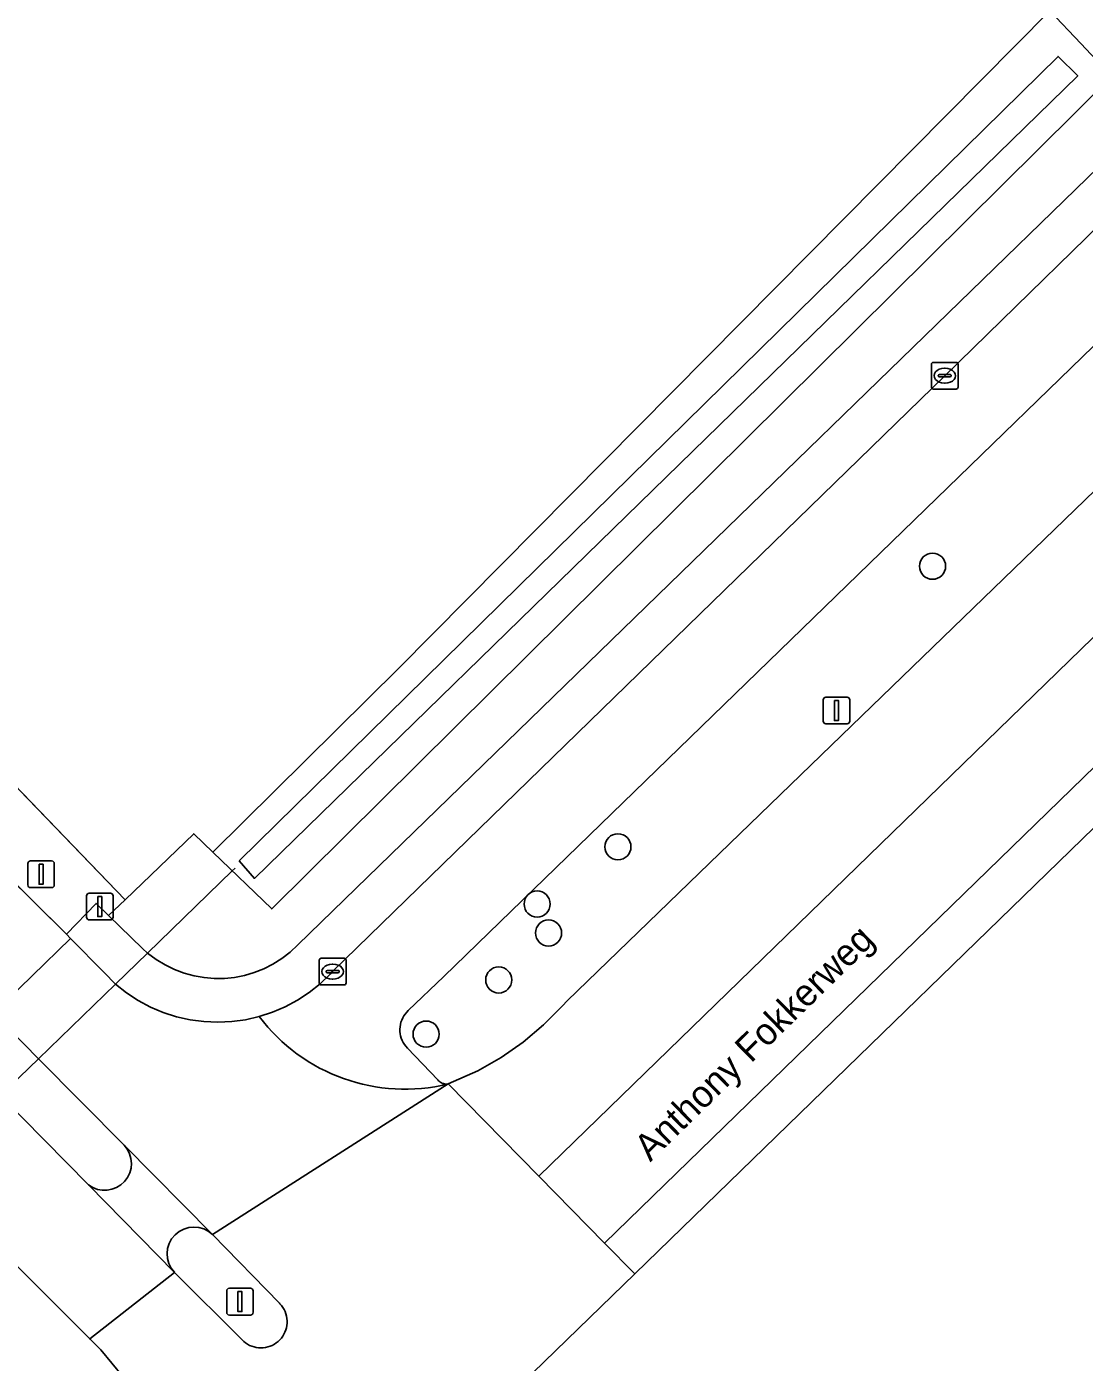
# Model space of a CAD drawing. Extents: x 156141 to 158132, y 385651 to 388333.
# Drawn here: x 156871.19 to 156910.79, y 385918.57 to 385968.56 of the extents above; entities that cross this region are included whole.
import ezdxf

# ---------------------------------------------------------------- set-up
doc = ezdxf.new("R2010")
doc.units = 0
for name, color, linetype in [('IMGEO_Berm_groen', 7, 'Continuous'), ('IMGEO_Boom', 7, 'Continuous'), ('IMGEO_Bouwland', 7, 'Continuous'), ('IMGEO_Duiker', 7, 'Continuous'), ('IMGEO_Fietspad_gesloten', 7, 'Continuous'), ('IMGEO_Fietspad_open', 7, 'Continuous'), ('IMGEO_Grasland_overig', 7, 'Continuous'), ('IMGEO_Groenvoorziening', 7, 'Continuous'), ('IMGEO_Kolk', 7, 'Continuous'), ('IMGEO_Lichtmast', 7, 'Continuous'), ('IMGEO_Oever', 7, 'Continuous'), ('IMGEO_Openbare_ruimte_label', 7, 'Continuous'), ('IMGEO_Rijbaan_lokaal_gesloten', 7, 'Continuous'), ('IMGEO_Rijbaan_lokaal_open', 7, 'Continuous'), ('IMGEO_Rijbaan_regionaal_gesloten', 7, 'Continuous'), ('IMGEO_Verkeersbordpaal', 7, 'Continuous'), ('IMGEO_Verkeerseiland_open', 7, 'Continuous'), ('IMGEO_Voetpad_open', 7, 'Continuous'), ('IMGEO_Waterloop', 7, 'Continuous')]:
    doc.layers.add(name, color=color, linetype=linetype)

msp = doc.modelspace()

# ---------------------------------------------------------------- linework, layer by layer
at = {"layer": 'IMGEO_Berm_groen'}
for points in [[(156930.003, 385974.918), (156886.812, 385933.009), (156885.478, 385931.729), (156885.417, 385931.668), (156885.361, 385931.601), (156885.312, 385931.53), (156885.269, 385931.455), (156885.233, 385931.376), (156885.204, 385931.294), (156885.183, 385931.21), (156885.169, 385931.124), (156885.163, 385931.038), (156885.165, 385930.951), (156885.174, 385930.865), (156885.191, 385930.78), (156885.216, 385930.697), (156885.248, 385930.616), (156885.287, 385930.539), (156885.333, 385930.465), (156885.385, 385930.396), (156885.45, 385930.325), (156886.578, 385929.141), (156886.602, 385929.112), (156886.629, 385929.086), (156886.659, 385929.062), (156886.69, 385929.041), (156886.723, 385929.022), (156886.757, 385929.007), (156886.793, 385928.995), (156886.83, 385928.986), (156886.867, 385928.98), (156886.904, 385928.978), (156886.942, 385928.979), (156886.974, 385928.983), (156888.076, 385929.479), (156888.949, 385929.977), (156889.774, 385930.55), (156890.545, 385931.196), (156891.255, 385931.907), (156891.426, 385932.099), (156932.102, 385971.44)], [(156874.788, 385918.027), (156873.964, 385919.033), (156873.553, 385919.437), (156867.279, 385925.705), (156865.275, 385923.762), (156865.686, 385922.841), (156867.113, 385917.692)]]:
    msp.add_lwpolyline(points, dxfattribs=at)
at = {"layer": 'IMGEO_Boom'}
for centre in [(156905.108, 385948.364), (156893.327, 385937.861), (156890.303, 385935.719), (156890.729, 385934.635), (156888.864, 385932.877), (156886.145, 385930.849)]:
    msp.add_circle(centre, 0.489, dxfattribs=at)
at = {"layer": 'IMGEO_Bouwland'}
msp.add_lwpolyline([(156850.754, 385950.548), (156852.463, 385950.284), (156855.652, 385949.539), (156859.447, 385948.19), (156861.712, 385947.117), (156863.64, 385946.028), (156865.038, 385945.128), (156867.151, 385943.555), (156868.367, 385942.514), (156869.913, 385941.02), (156874.876, 385935.88), (156877.444, 385938.348), (156878.163, 385937.657), (156885.11, 385944.531), (156909.503, 385969.158), (156915.884, 385975.312), (156925.124, 385983.726), (156925.232, 385984.523), (156902.704, 386022.826), (156897.961, 386029.254), (156853.147, 386019.451), (156848.312, 386019.157)], dxfattribs=at)
at = {"layer": 'IMGEO_Duiker'}
msp.add_lwpolyline([(156864.371, 385922.885), (156865.275, 385923.762), (156867.279, 385925.705), (156870.21, 385928.547), (156871.635, 385929.928), (156874.513, 385932.719), (156875.714, 385933.884), (156878.887, 385936.96), (156878.995, 385937.065)], dxfattribs=at)
at = {"layer": 'IMGEO_Fietspad_gesloten'}
for points in [[(156939.898, 385988.199), (156929.654, 385978.802), (156929.144, 385978.317), (156928.848, 385978.036), (156921.473, 385971.021), (156905.562, 385955.495), (156882.643, 385933.19), (156882.555, 385933.096), (156882.177, 385932.735), (156881.769, 385932.409), (156881.333, 385932.122), (156880.873, 385931.874), (156880.393, 385931.668), (156879.896, 385931.506)], [(156886.974, 385928.983), (156886.942, 385928.979), (156886.904, 385928.978), (156886.867, 385928.98), (156886.83, 385928.986), (156886.793, 385928.995), (156886.757, 385929.007), (156886.723, 385929.022), (156886.69, 385929.041), (156886.659, 385929.062), (156886.629, 385929.086), (156886.602, 385929.112), (156886.578, 385929.141), (156885.45, 385930.325), (156885.385, 385930.396), (156885.333, 385930.465), (156885.287, 385930.539), (156885.248, 385930.616), (156885.216, 385930.697), (156885.191, 385930.78), (156885.174, 385930.865), (156885.165, 385930.951), (156885.163, 385931.038), (156885.169, 385931.124), (156885.183, 385931.21), (156885.204, 385931.294), (156885.233, 385931.376), (156885.269, 385931.455), (156885.312, 385931.53), (156885.361, 385931.601), (156885.417, 385931.668), (156885.478, 385931.729), (156886.812, 385933.009), (156930.003, 385974.918)]]:
    msp.add_lwpolyline(points, dxfattribs=at)
msp.add_arc((156885.355, 385935.632), 6.843, 217.0806, 283.6816, dxfattribs=at)
at = {"layer": 'IMGEO_Fietspad_open'}
for points in [[(156878.148, 385923.344), (156874.845, 385926.689)], [(156873.5, 385925.207), (156876.718, 385921.932)]]:
    msp.add_lwpolyline(points, dxfattribs=at)
for centre, radius, start, end in [((156874.108, 385926.006), 1.004, 232.7427, 42.8063), ((156877.45, 385922.621), 1.005, 46.0245, 223.2497)]:
    msp.add_arc(centre, radius, start, end, dxfattribs=at)
at = {"layer": 'IMGEO_Grasland_overig'}
msp.add_lwpolyline([(156866.966, 385940.233), (156872.684, 385934.595), (156873.79, 385935.743), (156874.258, 385935.286), (156874.876, 385935.88), (156869.913, 385941.02), (156868.367, 385942.514), (156867.151, 385943.555), (156865.038, 385945.128), (156863.64, 385946.028), (156861.712, 385947.117), (156859.447, 385948.19), (156855.652, 385949.539), (156852.463, 385950.284), (156850.754, 385950.548), (156847.012, 385950.806), (156823.489, 385951.065), (156739.662, 385952.666), (156453.016, 385994.658)], dxfattribs=at)
at = {"layer": 'IMGEO_Groenvoorziening'}
for points in [[(156941.728, 385998.626), (156934.836, 385992.57), (156936.116, 385991.43), (156936.687, 385990.376), (156936.498, 385989.652), (156929.281, 385982.845), (156927.241, 385980.92), (156927.233, 385980.913), (156918.862, 385973.017), (156917.513, 385973.337), (156916.699, 385974.324), (156915.884, 385975.312), (156909.503, 385969.158), (156910.659, 385967.93), (156911.816, 385966.701), (156880.365, 385935.537), (156878.163, 385937.657), (156877.444, 385938.348), (156874.876, 385935.88), (156874.258, 385935.286), (156875.523, 385934.052), (156875.714, 385933.884)], [(156881.347, 385934.192), (156928.285, 385979.781), (156928.807, 385980.25), (156947.083, 385996.683)]]:
    msp.add_lwpolyline(points, dxfattribs=at)
msp.add_arc((156878.364, 385937.09), 4.159, 230.427, 315.8324, dxfattribs=at)
at = {"layer": 'IMGEO_Kolk'}
for p, q in [((156905.064, 385955.07), (156905.064, 385955.922)), ((156905.139, 385955.996), (156905.991, 385955.996)), ((156906.065, 385955.922), (156906.065, 385955.07)), ((156905.323, 385955.49), (156905.323, 385955.502)), ((156905.761, 385955.453), (156905.363, 385955.453)), ((156905.366, 385955.539), (156905.764, 385955.539)), ((156905.552, 385955.776), (156905.577, 385955.776)), ((156905.807, 385955.502), (156905.807, 385955.49)), ((156905.991, 385954.996), (156905.139, 385954.996)), ((156905.575, 385955.216), (156905.55, 385955.216)), ((156882.145, 385932.765), (156882.145, 385933.617)), ((156882.22, 385933.691), (156883.072, 385933.691)), ((156882.633, 385933.471), (156882.658, 385933.471)), ((156883.146, 385933.617), (156883.146, 385932.765)), ((156882.404, 385933.185), (156882.404, 385933.197)), ((156882.842, 385933.148), (156882.444, 385933.148)), ((156882.447, 385933.234), (156882.845, 385933.234)), ((156882.656, 385932.911), (156882.631, 385932.911)), ((156882.888, 385933.197), (156882.888, 385933.185)), ((156883.072, 385932.691), (156882.22, 385932.691))]:
    msp.add_line(p, q, dxfattribs=at)
for points in [[(156905.064, 385955.07), (156905.064, 385955.922)], [(156905.139, 385955.996), (156905.991, 385955.996)], [(156906.065, 385955.922), (156906.065, 385955.07)], [(156905.991, 385954.996), (156905.139, 385954.996)], [(156882.145, 385932.765), (156882.145, 385933.617)], [(156882.22, 385933.691), (156883.072, 385933.691)], [(156883.146, 385933.617), (156883.146, 385932.765)], [(156883.072, 385932.691), (156882.22, 385932.691)]]:
    msp.add_lwpolyline(points, dxfattribs=at)
for centre, radius, start, end in [((156905.141, 385955.92), 0.0765, 91.552, 178.448), ((156905.141, 385955.92), 0.0765, 91.552, 178.448), ((156905.989, 385955.92), 0.0765, 1.552, 88.448), ((156905.989, 385955.92), 0.0765, 1.552, 88.448), ((156905.363, 385955.499), 0.0403, 85.8775, 175.7526), ((156905.36, 385955.489), 0.0366, 178.938, 274.7102), ((156905.764, 385955.496), 0.043, 264.8664, 352.4533), ((156905.768, 385955.501), 0.0386, 1.7309, 96.639), ((156905.141, 385955.072), 0.0765, 181.552, 268.448), ((156905.141, 385955.072), 0.0765, 181.552, 268.448), ((156905.989, 385955.072), 0.0765, 271.552, 358.448), ((156905.989, 385955.072), 0.0765, 271.552, 358.448), ((156882.222, 385933.615), 0.0765, 91.552, 178.448), ((156882.222, 385933.615), 0.0765, 91.552, 178.448), ((156883.07, 385933.615), 0.0765, 1.552, 88.448), ((156883.07, 385933.615), 0.0765, 1.552, 88.448), ((156882.444, 385933.194), 0.0403, 85.8775, 175.7526), ((156882.441, 385933.184), 0.0366, 178.938, 274.7102), ((156882.845, 385933.191), 0.043, 264.8664, 352.4533), ((156882.849, 385933.196), 0.0386, 1.7309, 96.639), ((156882.222, 385932.767), 0.0765, 181.552, 268.448), ((156882.222, 385932.767), 0.0765, 181.552, 268.448), ((156883.07, 385932.767), 0.0765, 271.552, 358.448), ((156883.07, 385932.767), 0.0765, 271.552, 358.448)]:
    msp.add_arc(centre, radius, start, end, dxfattribs=at)
for centre, major_axis, ratio, start_param, end_param in [((156905.551, 385955.496), (-0.387, 0.002), 0.722429, 4.712389, 7.853982), ((156905.576, 385955.496), (-0.39, 0.002), 0.717154, 1.570796, 4.712389), ((156882.632, 385933.191), (-0.387, 0.002), 0.722429, 4.712389, 7.853982), ((156882.657, 385933.191), (-0.39, 0.002), 0.717154, 1.570796, 4.712389)]:
    msp.add_ellipse(centre, major_axis=major_axis, ratio=ratio, start_param=start_param, end_param=end_param, dxfattribs=at)
at = {"layer": 'IMGEO_Lichtmast'}
for p, q in [((156901.115, 385943.464), (156901.905, 385943.464)), ((156901.905, 385943.464), (156901.115, 385943.464)), ((156901.015, 385942.564), (156901.015, 385943.364)), ((156901.015, 385943.364), (156901.015, 385942.564)), ((156902.005, 385943.364), (156902.005, 385942.564)), ((156902.005, 385942.564), (156902.005, 385943.364)), ((156901.905, 385942.464), (156901.115, 385942.464)), ((156901.115, 385942.464), (156901.905, 385942.464)), ((156871.234, 385936.432), (156871.234, 385937.232)), ((156871.234, 385937.232), (156871.234, 385936.432)), ((156871.334, 385937.332), (156872.124, 385937.332)), ((156872.124, 385937.332), (156871.334, 385937.332)), ((156872.224, 385937.232), (156872.224, 385936.432)), ((156872.224, 385936.432), (156872.224, 385937.232)), ((156872.124, 385936.332), (156871.334, 385936.332)), ((156871.334, 385936.332), (156872.124, 385936.332)), ((156878.678, 385920.435), (156878.678, 385921.235)), ((156878.678, 385921.235), (156878.678, 385920.435)), ((156878.778, 385921.335), (156879.568, 385921.335)), ((156879.568, 385921.335), (156878.778, 385921.335)), ((156879.668, 385921.235), (156879.668, 385920.435)), ((156879.668, 385920.435), (156879.668, 385921.235)), ((156879.568, 385920.335), (156878.778, 385920.335)), ((156878.778, 385920.335), (156879.568, 385920.335))]:
    msp.add_line(p, q, dxfattribs=at)
for points in [[(156901.435, 385943.339), (156901.585, 385943.339), (156901.585, 385942.589), (156901.435, 385942.589), (156901.435, 385943.339)], [(156871.654, 385937.207), (156871.804, 385937.207), (156871.804, 385936.457), (156871.654, 385936.457), (156871.654, 385937.207)], [(156879.098, 385921.21), (156879.248, 385921.21), (156879.248, 385920.46), (156879.098, 385920.46), (156879.098, 385921.21)]]:
    msp.add_lwpolyline(points, dxfattribs=at)
for centre, start, end in [((156901.115, 385943.364), 90, 180), ((156901.115, 385943.364), 90, 180), ((156901.905, 385943.364), 0, 90), ((156901.905, 385943.364), 360, 90), ((156901.115, 385942.564), 180, 270), ((156901.115, 385942.564), 180, 270), ((156901.905, 385942.564), 270, 0), ((156901.905, 385942.564), 270, 0), ((156871.334, 385937.232), 90, 180), ((156871.334, 385937.232), 90, 180), ((156872.124, 385937.232), 0, 90), ((156872.124, 385937.232), 360, 90), ((156871.334, 385936.432), 180, 270), ((156871.334, 385936.432), 180, 270), ((156872.124, 385936.432), 270, 0), ((156872.124, 385936.432), 270, 0), ((156878.778, 385921.235), 90, 180), ((156878.778, 385921.235), 90, 180), ((156879.568, 385921.235), 0, 90), ((156879.568, 385921.235), 360, 90), ((156878.778, 385920.435), 180, 270), ((156878.778, 385920.435), 180, 270), ((156879.568, 385920.435), 270, 0), ((156879.568, 385920.435), 270, 0)]:
    msp.add_arc(centre, 0.1, start, end, dxfattribs=at)
at = {"layer": 'IMGEO_Oever'}
for points in [[(156909.503, 385969.158), (156885.11, 385944.531), (156878.163, 385937.657), (156880.365, 385935.537), (156911.816, 385966.701), (156910.659, 385967.93)], [(156879.147, 385937.336), (156909.805, 385967.446), (156910.544, 385966.727), (156879.719, 385936.678)]]:
    msp.add_lwpolyline(points, close=True, dxfattribs=at)
at = {"layer": 'IMGEO_Rijbaan_lokaal_gesloten'}
msp.add_lwpolyline([(156879.896, 385931.506), (156879.387, 385931.39), (156878.87, 385931.319), (156878.348, 385931.294), (156877.826, 385931.316), (156877.308, 385931.385), (156876.799, 385931.5), (156876.302, 385931.66), (156875.821, 385931.863), (156875.36, 385932.109), (156874.923, 385932.395), (156874.513, 385932.719), (156874.086, 385933.151), (156872.828, 385934.428), (156869.95, 385931.628), (156871.635, 385929.928), (156874.845, 385926.689), (156878.148, 385923.344), (156886.974, 385928.983)], dxfattribs=at)
msp.add_lwpolyline([(156873.5, 385925.207), (156870.21, 385928.547), (156868.557, 385930.225), (156865.574, 385927.365), (156866.774, 385926.21), (156867.279, 385925.705), (156873.553, 385919.437), (156876.718, 385921.932)], close=True, dxfattribs=at)
msp.add_arc((156885.355, 385935.632), 6.843, 217.0806, 283.6816, dxfattribs=at)
at = {"layer": 'IMGEO_Rijbaan_lokaal_open'}
msp.add_lwpolyline([(156869.95, 385931.628), (156872.828, 385934.428), (156872.684, 385934.595), (156866.966, 385940.233)], dxfattribs=at)
at = {"layer": 'IMGEO_Rijbaan_regionaal_gesloten'}
for points in [[(156934.501, 385968.404), (156934.45, 385968.491), (156932.494, 385971.832), (156932.102, 385971.44), (156891.426, 385932.099), (156891.255, 385931.907), (156890.545, 385931.196), (156889.774, 385930.55), (156888.949, 385929.977), (156888.076, 385929.479), (156886.974, 385928.983), (156890.369, 385925.526)], [(156936.323, 385965.294), (156934.501, 385968.404), (156890.369, 385925.526), (156892.83, 385923.021)], [(156893.955, 385921.876), (156937.167, 385963.852), (156936.323, 385965.294), (156892.83, 385923.021)]]:
    msp.add_lwpolyline(points, close=True, dxfattribs=at)
msp.add_lwpolyline([(156879.95, 385908.272), (156893.955, 385921.876), (156892.83, 385923.021), (156890.369, 385925.526), (156886.974, 385928.983), (156878.148, 385923.344), (156880.657, 385920.772), (156880.674, 385920.754), (156880.731, 385920.688), (156880.782, 385920.617), (156880.827, 385920.541), (156880.864, 385920.462), (156880.895, 385920.38), (156880.917, 385920.295), (156880.933, 385920.209), (156880.94, 385920.121), (156880.94, 385920.034), (156880.931, 385919.947), (156880.915, 385919.861), (156880.892, 385919.776), (156880.861, 385919.694), (156880.822, 385919.615), (156880.777, 385919.54), (156880.725, 385919.47), (156880.668, 385919.404), (156880.604, 385919.343), (156880.536, 385919.289), (156880.462, 385919.241), (156880.385, 385919.199), (156880.305, 385919.165), (156880.221, 385919.138), (156880.136, 385919.118), (156880.049, 385919.107), (156879.961, 385919.103), (156879.874, 385919.107), (156879.787, 385919.118), (156879.702, 385919.138), (156879.618, 385919.165), (156879.538, 385919.199), (156879.46, 385919.24), (156879.387, 385919.288), (156879.319, 385919.343), (156879.255, 385919.403), (156876.718, 385921.932), (156873.553, 385919.437), (156873.964, 385919.033), (156874.788, 385918.027)], dxfattribs=at)
at = {"layer": 'IMGEO_Verkeersbordpaal'}
for p, q in [((156873.433, 385935.224), (156873.433, 385936.024)), ((156873.433, 385936.024), (156873.433, 385935.224)), ((156873.533, 385936.124), (156874.323, 385936.124)), ((156874.323, 385936.124), (156873.533, 385936.124)), ((156874.423, 385936.024), (156874.423, 385935.224)), ((156874.423, 385935.224), (156874.423, 385936.024)), ((156874.323, 385935.124), (156873.533, 385935.124)), ((156873.533, 385935.124), (156874.323, 385935.124))]:
    msp.add_line(p, q, dxfattribs=at)
msp.add_lwpolyline([(156873.853, 385935.999), (156874.003, 385935.999), (156874.003, 385935.249), (156873.853, 385935.249), (156873.853, 385935.999)], dxfattribs=at)
for centre, start, end in [((156873.533, 385936.024), 90, 180), ((156873.533, 385936.024), 90, 180), ((156874.323, 385936.024), 0, 90), ((156874.323, 385936.024), 360, 90), ((156873.533, 385935.224), 180, 270), ((156873.533, 385935.224), 180, 270), ((156874.323, 385935.224), 270, 0), ((156874.323, 385935.224), 270, 0)]:
    msp.add_arc(centre, 0.1, start, end, dxfattribs=at)
at = {"layer": 'IMGEO_Verkeerseiland_open'}
for points in [[(156871.635, 385929.928), (156869.95, 385931.628)], [(156874.845, 385926.689), (156871.635, 385929.928)], [(156870.21, 385928.547), (156873.5, 385925.207)], [(156876.718, 385921.932), (156879.255, 385919.403), (156879.319, 385919.343), (156879.387, 385919.288), (156879.46, 385919.24), (156879.538, 385919.199), (156879.618, 385919.165), (156879.702, 385919.138), (156879.787, 385919.118), (156879.874, 385919.107), (156879.961, 385919.103), (156880.049, 385919.107), (156880.136, 385919.118), (156880.221, 385919.138), (156880.305, 385919.165), (156880.385, 385919.199), (156880.462, 385919.241), (156880.536, 385919.289), (156880.604, 385919.343), (156880.668, 385919.404), (156880.725, 385919.47), (156880.777, 385919.54), (156880.822, 385919.615), (156880.861, 385919.694), (156880.892, 385919.776), (156880.915, 385919.861), (156880.931, 385919.947), (156880.94, 385920.034), (156880.94, 385920.121), (156880.933, 385920.209), (156880.917, 385920.295), (156880.895, 385920.38), (156880.864, 385920.462), (156880.827, 385920.541), (156880.782, 385920.617), (156880.731, 385920.688), (156880.674, 385920.754), (156880.657, 385920.772), (156878.148, 385923.344)]]:
    msp.add_lwpolyline(points, dxfattribs=at)
for centre, radius, start, end in [((156874.108, 385926.006), 1.004, 232.7427, 42.8063), ((156877.45, 385922.621), 1.005, 46.0245, 223.2497)]:
    msp.add_arc(centre, radius, start, end, dxfattribs=at)
at = {"layer": 'IMGEO_Voetpad_open'}
for points in [[(156950.902, 386000), (156947.083, 385996.683), (156928.807, 385980.25), (156928.285, 385979.781), (156881.347, 385934.192)], [(156875.714, 385933.884), (156875.523, 385934.052), (156874.258, 385935.286), (156873.79, 385935.743), (156872.684, 385934.595), (156872.828, 385934.428), (156874.086, 385933.151), (156874.513, 385932.719), (156874.923, 385932.395), (156875.36, 385932.109), (156875.821, 385931.863), (156876.302, 385931.66), (156876.799, 385931.5), (156877.308, 385931.385), (156877.826, 385931.316), (156878.348, 385931.294), (156878.87, 385931.319), (156879.387, 385931.39), (156879.896, 385931.506), (156880.393, 385931.668), (156880.873, 385931.874), (156881.333, 385932.122), (156881.769, 385932.409), (156882.177, 385932.735), (156882.555, 385933.096), (156882.643, 385933.19), (156905.562, 385955.495), (156921.473, 385971.021)]]:
    msp.add_lwpolyline(points, dxfattribs=at)
msp.add_arc((156878.364, 385937.09), 4.159, 230.427, 315.8324, dxfattribs=at)
at = {"layer": 'IMGEO_Waterloop'}
msp.add_lwpolyline([(156879.147, 385937.336), (156879.719, 385936.678), (156910.544, 385966.727), (156909.805, 385967.446)], close=True, dxfattribs=at)

# ---------------------------------------------------------------- texts
at = {"layer": 'IMGEO_Openbare_ruimte_label'}
msp.add_text('Anthony Fokkerweg', height=1, rotation=44.3517, dxfattribs=at).set_placement((156894.536, 385926.046))

doc.saveas('drawing.dxf')
